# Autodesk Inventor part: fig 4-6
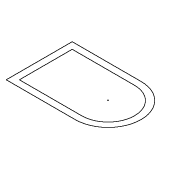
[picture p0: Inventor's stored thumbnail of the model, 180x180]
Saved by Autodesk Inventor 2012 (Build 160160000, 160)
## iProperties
Created: 2005-02
Part Number: fig 4-6
Document SubType Name: Modeling
Designer: CADCIM
Manufacturer: Standard
Standards Organization: Custom
Density: 1 g/cm^3
Material: Default
Author: CADCIM
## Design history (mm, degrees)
sketch "Sketch1"
  geometry: L1 (12.963, 23.563)-(-25.99, 23.563); L2 (-25.99, 23.563)-(-25.99, -13.729); L3 (-25.99, -13.729)-(12.963, -13.729); L4 (-22.275, 19.848)-(12.963, 19.848); L5 (12.963, -10.014)-(-22.275, -10.014); L6 (-22.275, -10.014)-(-22.275, 19.848); A1 r 18.646 centre (12.963, 4.917) between (12.963, -13.729) and (12.963, 23.563); A2 r 14.931 centre (12.963, 4.917) between (12.963, -10.014) and (12.963, 19.848)
  constraints: 12 end point, 4 point on circle, 2 centre point, 2 parallel, 2 perpendicular, 2 tangent, 1 horizontal, 4 other
